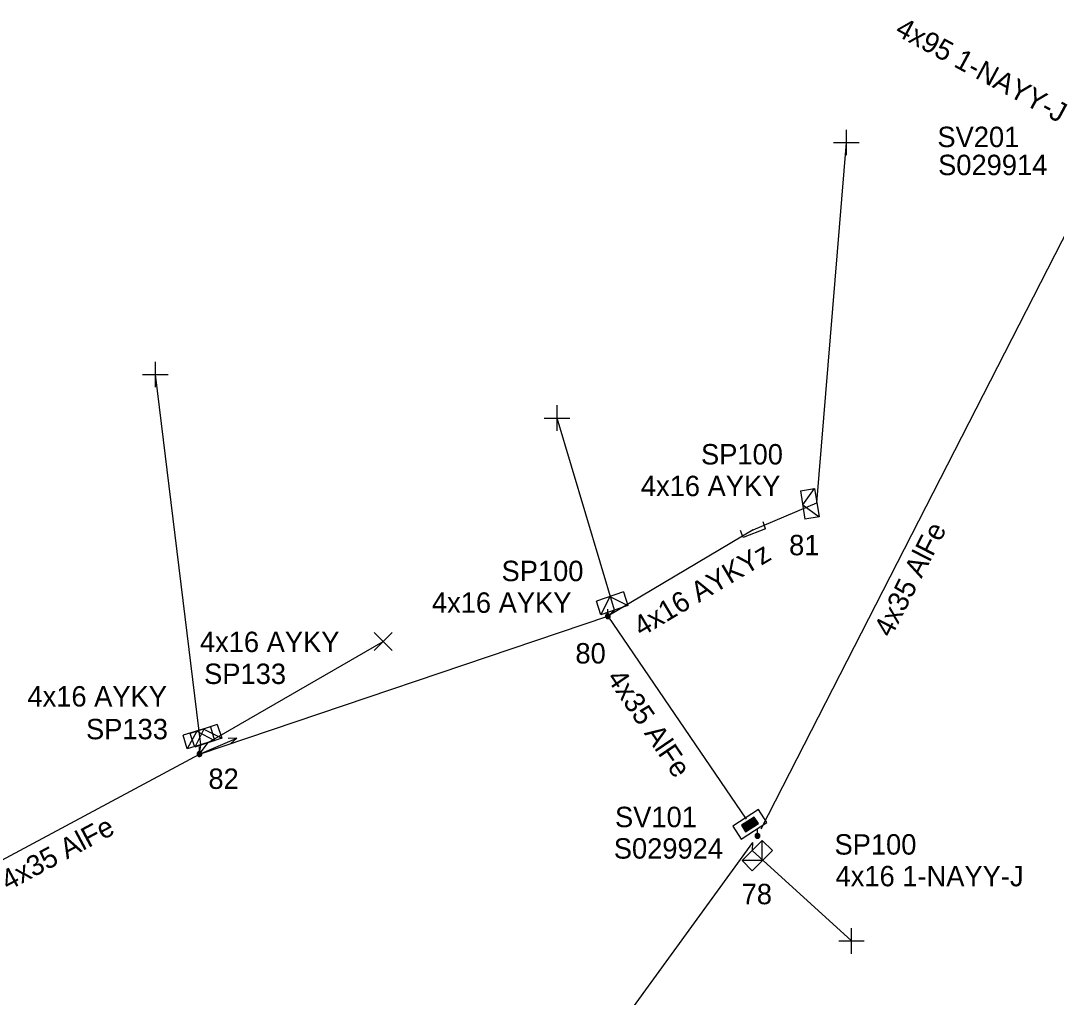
# Model space of a CAD drawing. Extents: x -788458 to -786145, y -1154772 to -1152372.
# Drawn here: x -787228.3 to -787177.6, y -1152522.8 to -1152474.9 of the extents above; entities that cross this region are included whole.
import ezdxf

# ---------------------------------------------------------------- set-up
doc = ezdxf.new("R2010")
doc.units = 0
for name, color, linetype in [('Vrstva 1', 7, 'Continuous'), ('Vrstva 13', 7, 'Continuous'), ('Vrstva 14', 7, 'Continuous'), ('Vrstva 2', 7, 'Continuous'), ('Vrstva 28', 7, 'Continuous'), ('Vrstva 29', 7, 'Continuous'), ('Vrstva 30', 7, 'Continuous'), ('Vrstva 31', 7, 'Continuous'), ('Vrstva 33', 7, 'Continuous'), ('Vrstva 34', 7, 'Continuous'), ('Vrstva 52', 7, 'Continuous'), ('Vrstva 53', 7, 'Continuous'), ('Vrstva 54', 7, 'Continuous'), ('Vrstva 55', 7, 'Continuous'), ('Vrstva 59', 7, 'Continuous'), ('Vrstva 6', 7, 'Continuous'), ('Vrstva 8', 7, 'Continuous'), ('Vrstva 9', 7, 'Continuous')]:
    doc.layers.add(name, color=color, linetype=linetype)

# ---------------------------------------------------------------- blocks, each defined once
blk = doc.blocks.new('NN560')
at = {"layer": 'Vrstva 2'}
for points in [[(1.999, -0.001), (1.59, 0.141)], [(0, -0.001), (1.999, -0.001)], [(1.999, -0.001), (1.59, -0.134)]]:
    blk.add_lwpolyline(points, dxfattribs=at)
blk = doc.blocks.new('NN800')
at = {"layer": 'Vrstva 1'}
for points in [[(-0.442, 0.442), (0.442, -0.442)], [(-0.442, -0.442), (0.442, 0.442)]]:
    blk.add_lwpolyline(points, dxfattribs=at)
blk = doc.blocks.new('NN620')
at = {"layer": 'Vrstva 8'}
for points in [[(0.752, 0.004), (-0.748, 0.004)], [(-0.748, 0.004), (-0.748, -0.746)], [(0.752, -0.746), (0.752, 0.004)], [(0.368, -0.18), (-0.376, -0.18)], [(-0.376, -0.18), (-0.376, -0.558)], [(0.321, -0.227), (-0.329, -0.227)], [(-0.329, -0.227), (-0.329, -0.51)], [(0.274, -0.274), (-0.281, -0.274)], [(-0.281, -0.274), (-0.281, -0.463)], [(-0.281, -0.463), (0.274, -0.463)], [(0.227, -0.321), (-0.234, -0.321)], [(-0.234, -0.321), (-0.234, -0.416)], [(-0.234, -0.416), (0.227, -0.416)], [(-0.193, -0.369), (0.185, -0.369)], [(0.227, -0.416), (0.227, -0.321)], [(0.274, -0.463), (0.274, -0.274)], [(0.321, -0.51), (0.321, -0.227)], [(0.368, -0.558), (0.368, -0.18)], [(-0.748, -0.746), (0.752, -0.746)], [(-0.376, -0.558), (0.368, -0.558)], [(-0.329, -0.51), (0.321, -0.51)]]:
    blk.add_lwpolyline(points, dxfattribs=at)
blk = doc.blocks.new('NN630')
at = {"layer": 'Vrstva 9'}
for points in [[(-0.003, -0.7), (-0.703, 0)], [(-0.703, -0.7), (-0.703, 0), (0.697, 0), (0.697, -0.7)], [(-0.003, -0.7), (0.697, 0)], [(-0.703, -0.7), (0.697, -0.7)]]:
    blk.add_lwpolyline(points, dxfattribs=at)
blk = doc.blocks.new('NN500')
at = {"layer": 'Vrstva 2'}
for points in [[(0, -0.24), (0.02, -0.23), (0.05, -0.23), (0.07, -0.22), (0.09, -0.22), (0.12, -0.2), (0.14, -0.19), (0.16, -0.18), (0.17, -0.16), (0.19, -0.14), (0.2, -0.12), (0.21, -0.1), (0.22, -0.07), (0.23, -0.05), (0.23, -0.02), (0.23, 0), (0.23, 0.02), (0.23, 0.05), (0.22, 0.07), (0.21, 0.1), (0.2, 0.12), (0.19, 0.14), (0.17, 0.16), (0.16, 0.17), (0.14, 0.19), (0.12, 0.2), (0.09, 0.21), (0.07, 0.22), (0.05, 0.23), (0.02, 0.23), (0, 0.23), (-0.03, 0.23), (-0.05, 0.23), (-0.07, 0.22), (-0.1, 0.21), (-0.12, 0.2), (-0.14, 0.19), (-0.16, 0.17), (-0.18, 0.16), (-0.19, 0.14), (-0.2, 0.12), (-0.22, 0.1), (-0.22, 0.07), (-0.23, 0.05), (-0.23, 0.02), (-0.24, 0), (-0.23, -0.02), (-0.23, -0.05), (-0.22, -0.07), (-0.22, -0.1), (-0.2, -0.12), (-0.19, -0.14), (-0.18, -0.16), (-0.16, -0.18), (-0.14, -0.19), (-0.12, -0.2), (-0.1, -0.22), (-0.07, -0.22), (-0.05, -0.23), (-0.03, -0.23), (0, -0.24)], [(0, -0.24), (0.02, -0.23), (0.05, -0.23), (0.07, -0.22), (0.09, -0.22), (0.12, -0.2), (0.14, -0.19), (0.16, -0.18), (0.17, -0.16), (0.19, -0.14), (0.2, -0.12), (0.21, -0.1), (0.22, -0.07), (0.23, -0.05), (0.23, -0.02), (0.23, 0), (0.23, 0.02), (0.23, 0.05), (0.22, 0.07), (0.21, 0.1), (0.2, 0.12), (0.19, 0.14), (0.17, 0.16), (0.16, 0.17), (0.14, 0.19), (0.12, 0.2), (0.09, 0.21), (0.07, 0.22), (0.05, 0.23), (0.02, 0.23), (0, 0.23), (-0.03, 0.23), (-0.05, 0.23), (-0.07, 0.22), (-0.1, 0.21), (-0.12, 0.2), (-0.14, 0.19), (-0.16, 0.17), (-0.18, 0.16), (-0.19, 0.14), (-0.2, 0.12), (-0.22, 0.1), (-0.22, 0.07), (-0.23, 0.05), (-0.23, 0.02), (-0.24, 0), (-0.23, -0.02), (-0.23, -0.05), (-0.22, -0.07), (-0.22, -0.1), (-0.2, -0.12), (-0.19, -0.14), (-0.18, -0.16), (-0.16, -0.18), (-0.14, -0.19), (-0.12, -0.2), (-0.1, -0.22), (-0.07, -0.22), (-0.05, -0.23), (-0.03, -0.23), (0, -0.24)], [(0, -0.21), (0.02, -0.2), (0.04, -0.2), (0.06, -0.2), (0.08, -0.19), (0.1, -0.18), (0.12, -0.17), (0.14, -0.15), (0.15, -0.14), (0.16, -0.12), (0.18, -0.1), (0.19, -0.08), (0.19, -0.06), (0.2, -0.04), (0.2, -0.02), (0.2, 0), (0.2, 0.02), (0.2, 0.04), (0.19, 0.06), (0.19, 0.08), (0.18, 0.1), (0.16, 0.12), (0.15, 0.14), (0.14, 0.15), (0.12, 0.17), (0.1, 0.18), (0.08, 0.19), (0.06, 0.19), (0.04, 0.2), (0.02, 0.2), (0, 0.2), (-0.02, 0.2), (-0.04, 0.2), (-0.06, 0.19), (-0.08, 0.19), (-0.1, 0.18), (-0.12, 0.17), (-0.14, 0.15), (-0.15, 0.14), (-0.17, 0.12), (-0.18, 0.1), (-0.19, 0.08), (-0.2, 0.06), (-0.2, 0.04), (-0.21, 0.02), (-0.21, 0), (-0.21, -0.02), (-0.2, -0.04), (-0.2, -0.06), (-0.19, -0.08), (-0.18, -0.1), (-0.17, -0.12), (-0.15, -0.14), (-0.14, -0.15), (-0.12, -0.17), (-0.1, -0.18), (-0.08, -0.19), (-0.06, -0.2), (-0.04, -0.2), (-0.02, -0.2), (0, -0.21)], [(0, -0.18), (0.02, -0.18), (0.04, -0.17), (0.05, -0.17), (0.07, -0.16), (0.09, -0.15), (0.1, -0.14), (0.12, -0.13), (0.13, -0.12), (0.14, -0.1), (0.15, -0.09), (0.16, -0.07), (0.17, -0.05), (0.17, -0.04), (0.17, -0.02), (0.17, 0), (0.17, 0.02), (0.17, 0.04), (0.17, 0.05), (0.16, 0.07), (0.15, 0.09), (0.14, 0.1), (0.13, 0.12), (0.12, 0.13), (0.1, 0.14), (0.09, 0.15), (0.07, 0.16), (0.05, 0.17), (0.04, 0.17), (0.02, 0.17), (0, 0.18), (-0.02, 0.17), (-0.04, 0.17), (-0.06, 0.17), (-0.07, 0.16), (-0.09, 0.15), (-0.1, 0.14), (-0.12, 0.13), (-0.13, 0.12), (-0.14, 0.1), (-0.15, 0.09), (-0.16, 0.07), (-0.17, 0.05), (-0.17, 0.04), (-0.18, 0.02), (-0.18, 0), (-0.18, -0.02), (-0.17, -0.04), (-0.17, -0.05), (-0.16, -0.07), (-0.15, -0.09), (-0.14, -0.1), (-0.13, -0.12), (-0.12, -0.13), (-0.1, -0.14), (-0.09, -0.15), (-0.07, -0.16), (-0.06, -0.17), (-0.04, -0.17), (-0.02, -0.18), (0, -0.18)], [(0, -0.15), (0.01, -0.15), (0.03, -0.14), (0.04, -0.14), (0.06, -0.13), (0.07, -0.13), (0.08, -0.12), (0.1, -0.11), (0.11, -0.1), (0.12, -0.09), (0.13, -0.07), (0.13, -0.06), (0.14, -0.05), (0.14, -0.03), (0.14, -0.02), (0.14, 0), (0.14, 0.01), (0.14, 0.03), (0.14, 0.04), (0.13, 0.06), (0.13, 0.07), (0.12, 0.09), (0.11, 0.1), (0.1, 0.11), (0.08, 0.12), (0.07, 0.13), (0.06, 0.13), (0.04, 0.14), (0.03, 0.14), (0.01, 0.14), (0, 0.15), (-0.02, 0.14), (-0.03, 0.14), (-0.05, 0.14), (-0.06, 0.13), (-0.07, 0.13), (-0.09, 0.12), (-0.1, 0.11), (-0.11, 0.1), (-0.12, 0.09), (-0.13, 0.07), (-0.13, 0.06), (-0.14, 0.04), (-0.14, 0.03), (-0.15, 0.01), (-0.15, 0), (-0.15, -0.02), (-0.14, -0.03), (-0.14, -0.05), (-0.13, -0.06), (-0.13, -0.07), (-0.12, -0.09), (-0.11, -0.1), (-0.1, -0.11), (-0.09, -0.12), (-0.07, -0.13), (-0.06, -0.13), (-0.05, -0.14), (-0.03, -0.14), (-0.02, -0.15), (0, -0.15)], [(0, -0.12), (0.01, -0.12), (0.02, -0.11), (0.03, -0.11), (0.05, -0.11), (0.06, -0.1), (0.07, -0.09), (0.08, -0.09), (0.09, -0.08), (0.09, -0.07), (0.1, -0.06), (0.11, -0.05), (0.11, -0.04), (0.11, -0.02), (0.11, -0.01), (0.12, 0), (0.11, 0.01), (0.11, 0.02), (0.11, 0.04), (0.11, 0.05), (0.1, 0.06), (0.09, 0.07), (0.09, 0.08), (0.08, 0.09), (0.07, 0.09), (0.06, 0.1), (0.05, 0.11), (0.03, 0.11), (0.02, 0.11), (0.01, 0.12), (0, 0.12), (-0.01, 0.12), (-0.03, 0.11), (-0.04, 0.11), (-0.05, 0.11), (-0.06, 0.1), (-0.07, 0.09), (-0.08, 0.09), (-0.09, 0.08), (-0.1, 0.07), (-0.1, 0.06), (-0.11, 0.05), (-0.11, 0.04), (-0.12, 0.02), (-0.12, 0.01), (-0.12, 0), (-0.12, -0.01), (-0.12, -0.02), (-0.11, -0.04), (-0.11, -0.05), (-0.1, -0.06), (-0.1, -0.07), (-0.09, -0.08), (-0.08, -0.09), (-0.07, -0.09), (-0.06, -0.1), (-0.05, -0.11), (-0.04, -0.11), (-0.03, -0.11), (-0.01, -0.12), (0, -0.12)], [(0, -0.09), (0.01, -0.09), (0.02, -0.09), (0.03, -0.08), (0.03, -0.08), (0.04, -0.08), (0.05, -0.07), (0.06, -0.07), (0.06, -0.06), (0.07, -0.05), (0.07, -0.04), (0.08, -0.04), (0.08, -0.03), (0.08, -0.02), (0.09, -0.01), (0.09, 0), (0.09, 0.01), (0.08, 0.02), (0.08, 0.03), (0.08, 0.03), (0.07, 0.04), (0.07, 0.05), (0.06, 0.06), (0.06, 0.06), (0.05, 0.07), (0.04, 0.07), (0.03, 0.08), (0.03, 0.08), (0.02, 0.08), (0.01, 0.09), (0, 0.09), (-0.01, 0.09), (-0.02, 0.08), (-0.03, 0.08), (-0.04, 0.08), (-0.04, 0.07), (-0.05, 0.07), (-0.06, 0.06), (-0.07, 0.06), (-0.07, 0.05), (-0.08, 0.04), (-0.08, 0.03), (-0.08, 0.03), (-0.09, 0.02), (-0.09, 0.01), (-0.09, 0), (-0.09, -0.01), (-0.09, -0.02), (-0.08, -0.03), (-0.08, -0.04), (-0.08, -0.04), (-0.07, -0.05), (-0.07, -0.06), (-0.06, -0.07), (-0.05, -0.07), (-0.04, -0.08), (-0.04, -0.08), (-0.03, -0.08), (-0.02, -0.09), (-0.01, -0.09), (0, -0.09)], [(0, -0.06), (0, -0.06), (0.01, -0.06), (0.02, -0.05), (0.02, -0.05), (0.03, -0.05), (0.03, -0.05), (0.04, -0.04), (0.04, -0.04), (0.05, -0.03), (0.05, -0.03), (0.05, -0.02), (0.05, -0.02), (0.05, -0.01), (0.06, -0.01), (0.06, 0), (0.06, 0.01), (0.05, 0.01), (0.05, 0.02), (0.05, 0.02), (0.05, 0.03), (0.05, 0.03), (0.04, 0.04), (0.04, 0.04), (0.03, 0.05), (0.03, 0.05), (0.02, 0.05), (0.02, 0.05), (0.01, 0.06), (0, 0.06), (0, 0.06), (-0.01, 0.06), (-0.01, 0.06), (-0.02, 0.05), (-0.02, 0.05), (-0.03, 0.05), (-0.03, 0.05), (-0.04, 0.04), (-0.04, 0.04), (-0.05, 0.03), (-0.05, 0.03), (-0.05, 0.02), (-0.06, 0.02), (-0.06, 0.01), (-0.06, 0.01), (-0.06, 0), (-0.06, -0.01), (-0.06, -0.01), (-0.06, -0.02), (-0.05, -0.02), (-0.05, -0.03), (-0.05, -0.03), (-0.04, -0.04), (-0.04, -0.04), (-0.03, -0.05), (-0.03, -0.05), (-0.02, -0.05), (-0.02, -0.05), (-0.01, -0.06), (-0.01, -0.06), (0, -0.06)], [(0, -0.03), (0, -0.03), (0, -0.03), (0.01, -0.03), (0.01, -0.03), (0.01, -0.02), (0.02, -0.02), (0.02, -0.02), (0.02, -0.02), (0.02, -0.02), (0.02, -0.01), (0.02, -0.01), (0.03, -0.01), (0.03, -0.01), (0.03, 0), (0.03, 0), (0.03, 0), (0.03, 0.01), (0.03, 0.01), (0.02, 0.01), (0.02, 0.01), (0.02, 0.02), (0.02, 0.02), (0.02, 0.02), (0.02, 0.02), (0.01, 0.02), (0.01, 0.02), (0.01, 0.03), (0, 0.03), (0, 0.03), (0, 0.03), (0, 0.03), (-0.01, 0.03), (-0.01, 0.03), (-0.01, 0.02), (-0.02, 0.02), (-0.02, 0.02), (-0.02, 0.02), (-0.02, 0.02), (-0.02, 0.02), (-0.03, 0.01), (-0.03, 0.01), (-0.03, 0.01), (-0.03, 0.01), (-0.03, 0), (-0.03, 0), (-0.03, 0), (-0.03, -0.01), (-0.03, -0.01), (-0.03, -0.01), (-0.03, -0.01), (-0.02, -0.02), (-0.02, -0.02), (-0.02, -0.02), (-0.02, -0.02), (-0.02, -0.02), (-0.01, -0.03), (-0.01, -0.03), (-0.01, -0.03), (0, -0.03), (0, -0.03)], [(0.23, 0), (0.7, 0)]]:
    blk.add_lwpolyline(points, dxfattribs=at)
blk = doc.blocks.new('NN515')
at = {"layer": 'Vrstva 2'}
for points in [[(-0.59, 0.176), (0.591, 0.176)], [(-0.59, 0.176), (-0.59, -0.179)], [(0.591, 0.176), (0.591, -0.179)]]:
    blk.add_lwpolyline(points, dxfattribs=at)

msp = doc.modelspace()

# ---------------------------------------------------------------- linework, layer by layer
at = {"layer": 'Vrstva 1'}
for points in [[(-787175.56, -1152482.27), (-787192.07, -1152514.518)], [(-787250.63, -1152521.8), (-787234.5, -1152518.83), (-787219.59, -1152510.84), (-787199.57, -1152504.09)], [(-787199.57, -1152504.09), (-787192.795, -1152514.036)], [(-787192.479, -1152515.179), (-787204.31, -1152531.45), (-787211.57, -1152547.04), (-787217.9, -1152560.27), (-787220.49, -1152567.22), (-787223.86, -1152575.79)]]:
    msp.add_lwpolyline(points, dxfattribs=at)
at = {"layer": 'Vrstva 52'}
for points in [[(-787192.45, -1152499.85), (-787189.33, -1152498.53)], [(-787192.45, -1152499.85), (-787199.57, -1152504.09)], [(-787199.57, -1152504.09), (-787199.25, -1152503.79)], [(-787219.59, -1152510.84), (-787219.16, -1152510.28)], [(-787219.59, -1152510.84), (-787219.52, -1152510.39)]]:
    msp.add_lwpolyline(points, dxfattribs=at)
at = {"layer": 'Vrstva 59'}
for points in [[(-787189.33, -1152498.53), (-787187.88, -1152480.88)], [(-787219.52, -1152510.39), (-787221.75, -1152492.25)], [(-787199.25, -1152503.79), (-787202.06, -1152494.38)], [(-787219.16, -1152510.28), (-787210.578, -1152505.331)], [(-787192.494, -1152515.564), (-787187.63, -1152520)]]:
    msp.add_lwpolyline(points, dxfattribs=at)
at = {"layer": 'Vrstva 8'}
msp.add_lwpolyline([(-787192.479, -1152515.179), (-787192.494, -1152515.564)], dxfattribs=at)

# ---------------------------------------------------------------- block references
at = {"layer": 'Vrstva 13'}
for name, p, rotation in [('NN515', (-787192.45, -1152499.85), -159.0095167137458), ('NN560', (-787219.59, -1152510.84), 23.09840829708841)]:
    msp.add_blockref(name, p, dxfattribs=dict(at, rotation=rotation))
at = {"layer": 'Vrstva 13', "xscale": 0.5, "yscale": 0.5, "rotation": 90}
for p in [(-787199.57, -1152504.09), (-787219.59, -1152510.84), (-787192.24, -1152514.85)]:
    msp.add_blockref('NN500', p, dxfattribs=at)
at = {"layer": 'Vrstva 28', "rotation": -147.03027968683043}
msp.add_blockref('NN620', (-787192.411, -1152514.599), dxfattribs=at)
at = {"layer": 'Vrstva 31'}
for p, rotation in [((-787189.33, -1152498.53), -81.02737340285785), ((-787199.25, -1152503.79), -161.14684120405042), ((-787219.52, -1152510.39), -163.00917687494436), ((-787219.16, -1152510.28), -161.56505124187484), ((-787192.494, -1152515.564), 45)]:
    msp.add_blockref('NN630', p, dxfattribs=dict(at, rotation=rotation))
at = {"layer": 'Vrstva 34', "rotation": 45}
for p in [(-787187.88, -1152480.88), (-787221.75, -1152492.25), (-787202.06, -1152494.38), (-787187.63, -1152520)]:
    msp.add_blockref('NN800', p, dxfattribs=at)
at = {"layer": 'Vrstva 34'}
msp.add_blockref('NN800', (-787210.578, -1152505.331), dxfattribs=at)

# ---------------------------------------------------------------- texts
at = {"layer": 'Vrstva 14'}
for s, p in [('81', (-787190.686, -1152501.104)), ('80', (-787201.161, -1152506.406)), ('82', (-787219.149, -1152512.549)), ('78', (-787193.014, -1152518.2))]:
    msp.add_text(s, height=1, dxfattribs=at).set_placement(p)
at = {"layer": 'Vrstva 2'}
for rotation, p in [(62.889, (-787185.691, -1152505.18)), (304.264, (-787199.66, -1152507.119)), (28.186, (-787228.973, -1152517.559))]:
    msp.add_text('4x35 AlFe', height=1, rotation=rotation, dxfattribs=at).set_placement(p)
at = {"layer": 'Vrstva 29'}
for s, p in [('S029914', (-787183.384, -1152482.482)), ('S029924', (-787199.28, -1152515.966))]:
    msp.add_text(s, height=1, dxfattribs=at).set_placement(p)
at = {"layer": 'Vrstva 30'}
for s, p in [('SV201', (-787183.419, -1152481.108)), ('SV101', (-787199.221, -1152514.424))]:
    msp.add_text(s, height=1, dxfattribs=at).set_placement(p)
at = {"layer": 'Vrstva 33'}
for s, p in [('SP100', (-787195.005, -1152496.656)), ('SP100', (-787204.782, -1152502.372)), ('SP133', (-787219.359, -1152507.411)), ('SP133', (-787225.149, -1152510.118)), ('SP100', (-787188.462, -1152515.769))]:
    msp.add_text(s, height=1, dxfattribs=at).set_placement(p)
at = {"layer": 'Vrstva 53'}
msp.add_text('4x16 AYKYz', height=1, rotation=30.774, dxfattribs=at).set_placement((-787197.93, -1152505.12))
at = {"layer": 'Vrstva 54'}
for p in [(-787197.954, -1152498.208), (-787208.195, -1152503.923), (-787219.566, -1152505.846), (-787228.02, -1152508.514)]:
    msp.add_text('4x16 AYKY', height=1, dxfattribs=at).set_placement(p)
at = {"layer": 'Vrstva 55'}
msp.add_text('4x16 1-NAYY-J', height=1, dxfattribs=at).set_placement((-787188.41, -1152517.321))
at = {"layer": 'Vrstva 6'}
msp.add_text('4x95 1-NAYY-J', height=1, rotation=331.708, dxfattribs=at).set_placement((-787185.548, -1152475.583))

doc.saveas('drawing.dxf')
